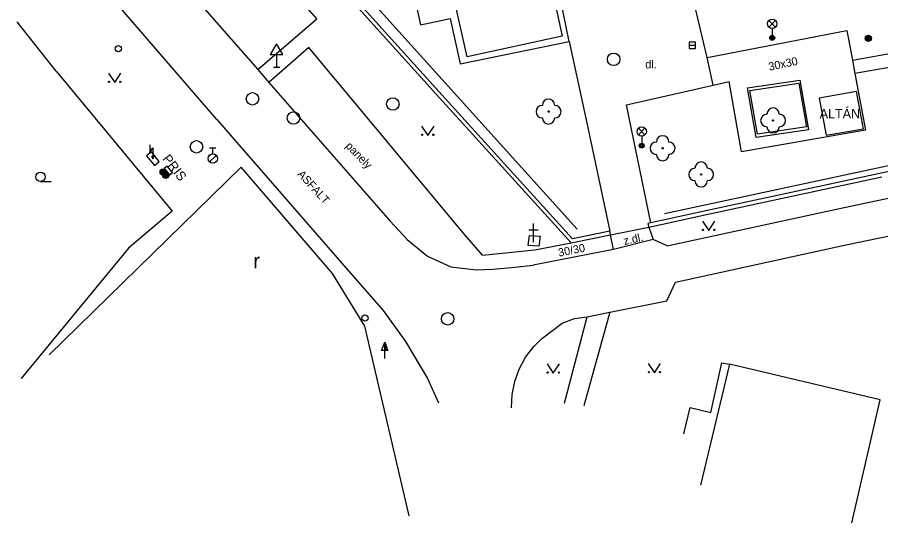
# Model space of a CAD drawing. Extents: x -539244 to -537359, y -1183785 to -1181851.
# Drawn here: x -538206 to -538136.7, y -1183773.1 to -1183732.5 of the extents above; entities that cross this region are included whole.
import ezdxf

# ---------------------------------------------------------------- set-up
doc = ezdxf.new("R2010")
doc.units = 0
for name, color, linetype in [('Vrstva 10', 7, 'Continuous'), ('Vrstva 11', 7, 'Continuous'), ('Vrstva 21', 7, 'Continuous'), ('Vrstva 22', 7, 'Continuous'), ('Vrstva 23', 7, 'Continuous'), ('Vrstva 24', 7, 'Continuous'), ('Vrstva 25', 7, 'Continuous'), ('Vrstva 27', 7, 'Continuous'), ('Vrstva 28', 7, 'Continuous'), ('Vrstva 33', 7, 'Continuous'), ('Vrstva 34', 7, 'Continuous'), ('Vrstva 36', 7, 'Continuous'), ('Vrstva 40', 7, 'Continuous'), ('Vrstva 41', 7, 'Continuous'), ('Vrstva 5', 7, 'Continuous'), ('Vrstva 7', 7, 'Continuous'), ('Vrstva 8', 7, 'Continuous')]:
    doc.layers.add(name, color=color, linetype=linetype)

msp = doc.modelspace()

# ---------------------------------------------------------------- linework, layer by layer
at = {"layer": 'Vrstva 10'}
for p, q in [((-538202.16, -1183718.96), (-538186.72, -1183736.74)), ((-538190.01, -1183740.74), (-538198.482, -1183730.899)), ((-538186.72, -1183736.74), (-538185.82, -1183737.77)), ((-538185.82, -1183737.77), (-538176.1, -1183748.9)), ((-538147.92, -1183743.33), (-538148.9, -1183737.7)), ((-538190.01, -1183740.74), (-538179.99, -1183752.25)), ((-538137.98, -1183741.61), (-538147.92, -1183743.33)), ((-538154.99, -1183750.36), (-538158.19, -1183751.17)), ((-538153.88, -1183750.89), (-538154.99, -1183750.36)), ((-538158.19, -1183751.17), (-538164.63, -1183752.42)), ((-538179.99, -1183752.25), (-538176.67, -1183756.07)), ((-538160.29, -1183756.56), (-538158.47, -1183756.19)), ((-538163.96, -1183758.34), (-538162.3, -1183757.08))]:
    msp.add_line(p, q, dxfattribs=at)
for points in [[(-538139.46, -1183733.6), (-538139.016, -1183735.982), (-538138.818, -1183737.042), (-538137.98, -1183741.61)], [(-538176.1, -1183748.9), (-538174.72, -1183750.36), (-538173.1, -1183751.7), (-538171.24, -1183752.57), (-538169.17, -1183752.81), (-538167.87, -1183752.75)], [(-538167.87, -1183752.75), (-538166.09, -1183752.58), (-538164.63, -1183752.42)], [(-538158.47, -1183756.19), (-538153.9, -1183755.3), (-538153.21, -1183753.79)], [(-538176.67, -1183756.07), (-538174.86, -1183758.55), (-538173.09, -1183761.51), (-538172.22, -1183763.48)], [(-538162.3, -1183757.08), (-538161.31, -1183756.72), (-538160.29, -1183756.56)], [(-538166.37, -1183763.88), (-538166.317, -1183762.812), (-538166.105, -1183761.763), (-538165.75, -1183760.78), (-538165.229, -1183759.818), (-538164.584, -1183758.965), (-538163.96, -1183758.34)]]:
    msp.add_lwpolyline(points, dxfattribs=at)
at = {"layer": 'Vrstva 11'}
for p, q in [((-538175.775, -1183723.409), (-538173.67, -1183733.152)), ((-538181.99, -1183732.68), (-538189.13, -1183724.3)), ((-538161.73, -1183734.48), (-538162.88, -1183729)), ((-538150.66, -1183735.78), (-538151.78, -1183731.05)), ((-538186.72, -1183736.74), (-538181.99, -1183732.68)), ((-538150.66, -1183735.78), (-538139.46, -1183733.6)), ((-538170.48, -1183736.29), (-538161.73, -1183734.48)), ((-538161.73, -1183734.48), (-538160.37, -1183740.76)), ((-538182.63, -1183734.98), (-538185.82, -1183737.77)), ((-538170.12, -1183750), (-538182.63, -1183734.98)), ((-538139.016, -1183735.982), (-538133.12, -1183734.92)), ((-538150.18, -1183737.98), (-538150.66, -1183735.78)), ((-538132.88, -1183736.01), (-538138.818, -1183737.042)), ((-538157.14, -1183739.56), (-538150.18, -1183737.98)), ((-538150.18, -1183737.98), (-538148.9, -1183737.7)), ((-538155.192, -1183749.027), (-538157.14, -1183739.56)), ((-538160.37, -1183740.76), (-538158.478, -1183749.708)), ((-538140.04, -1183747.88), (-538124.12, -1183744.52)), ((-538139.41, -1183750.76), (-538123.61, -1183747.54)), ((-538153.88, -1183750.89), (-538140.04, -1183747.88)), ((-538155.36, -1183749.37), (-538154.99, -1183750.36)), ((-538168.69, -1183751.62), (-538170.12, -1183750)), ((-538158.19, -1183751.17), (-538158.42, -1183750)), ((-538153.21, -1183753.79), (-538139.41, -1183750.76)), ((-538162.11, -1183763.5), (-538160.29, -1183756.56)), ((-538158.47, -1183756.19), (-538160.57, -1183763.71))]:
    msp.add_line(p, q, dxfattribs=at)
for points in [[(-538173.67, -1183733.152), (-538171.296, -1183732.645), (-538170.48, -1183736.29)], [(-538147.42, -1183738.21), (-538143.23, -1183737.59), (-538142.54, -1183741.56)], [(-538146.63, -1183741.91), (-538147.25, -1183738.41), (-538143.32, -1183737.829)], [(-538143.32, -1183737.829), (-538142.71, -1183741.34), (-538146.63, -1183741.91)], [(-538142.54, -1183741.56), (-538146.73, -1183742.18), (-538147.42, -1183738.21)], [(-538164.17, -1183750.9), (-538165.02, -1183750.85), (-538164.92, -1183750.04), (-538164.07, -1183750.09), (-538164.17, -1183750.9)], [(-538168.69, -1183751.62), (-538164.48, -1183751.21), (-538161.59, -1183750.64)], [(-538152.53, -1183765.96), (-538152.04, -1183763.85), (-538150.37, -1183764.24), (-538149.48, -1183760.26), (-538148.87, -1183760.36)]]:
    msp.add_lwpolyline(points, dxfattribs=at)
at = {"layer": 'Vrstva 21'}
for p, q in [((-538161.1, -1183749.528), (-538185.827, -1183722.097)), ((-538154.081, -1183748.272), (-538106.499, -1183738.062))]:
    msp.add_line(p, q, dxfattribs=at)
at = {"layer": 'Vrstva 22'}
for centre in [(-538163.39, -1183740.11), (-538145.38, -1183740.82), (-538154.24, -1183743.05), (-538151.15, -1183745.15)]:
    msp.add_circle(centre, 0.05, dxfattribs=at)
for centre, start, end in [((-538163.39, -1183739.61), 0, 180), ((-538163.89, -1183740.11), 90, 270), ((-538162.89, -1183740.11), 270, 90), ((-538145.38, -1183740.32), 0, 180), ((-538163.39, -1183740.61), 180, 0), ((-538145.88, -1183740.82), 90, 270), ((-538144.88, -1183740.82), 270, 90), ((-538145.38, -1183741.32), 180, 0), ((-538154.24, -1183742.55), 0, 180), ((-538154.74, -1183743.05), 90, 270), ((-538153.74, -1183743.05), 270, 90), ((-538154.24, -1183743.55), 180, 0), ((-538151.15, -1183744.65), 0, 180), ((-538151.65, -1183745.15), 90, 270), ((-538150.65, -1183745.15), 270, 90), ((-538151.15, -1183745.65), 180, 0)]:
    msp.add_arc(centre, 0.5, start, end, dxfattribs=at)
at = {"layer": 'Vrstva 23'}
for p, q in [((-538188.06, -1183744.58), (-538203.46, -1183759.62)), ((-538180.71, -1183753.11), (-538188.06, -1183744.58)), ((-538178.14, -1183757.31), (-538180.71, -1183753.11)), ((-538174.57, -1183772.54), (-538178.14, -1183757.31))]:
    msp.add_line(p, q, dxfattribs=at)
at = {"layer": 'Vrstva 24'}
for p, q in [((-538195.38, -1183742.764), (-538195.38, -1183743.39)), ((-538195.38, -1183743.39), (-538195.13, -1183743.015)), ((-538195.24, -1183743.645), (-538195.13, -1183743.89)), ((-538195.13, -1183743.015), (-538195.13, -1183743.89)), ((-538195.13, -1183743.89), (-538195.02, -1183743.645))]:
    msp.add_line(p, q, dxfattribs=at)
msp.add_lwpolyline([(-538194.622, -1183744.124), (-538195.248, -1183743.344), (-538195.638, -1183743.656), (-538195.012, -1183744.436)], close=True, dxfattribs=at)
msp.add_lwpolyline([(-538193.98, -1183744.48), (-538194.221, -1183744.683), (-538193.791, -1183745.193), (-538193.55, -1183744.99), (-538193.98, -1183744.48)], dxfattribs=at)
at = {"layer": 'Vrstva 25'}
for centre, radius in [((-538137.74, -1183734.23), 0.25), ((-538137.74, -1183734.23), 0.2), ((-538137.74, -1183734.23), 0.15), ((-538137.74, -1183734.23), 0.1), ((-538137.74, -1183734.23), 0.05), ((-538194.31, -1183744.96), 0.25), ((-538194.31, -1183744.96), 0.2), ((-538194.31, -1183744.96), 0.15), ((-538194.31, -1183744.96), 0.1), ((-538194.31, -1183744.96), 0.05), ((-538194.1, -1183745.23), 0.25), ((-538194.1, -1183745.23), 0.2), ((-538194.1, -1183745.23), 0.15), ((-538194.1, -1183745.23), 0.1), ((-538194.1, -1183745.23), 0.05)]:
    msp.add_circle(centre, radius, dxfattribs=at)
at = {"layer": 'Vrstva 27'}
msp.add_line((-538152.11, -1183734.79), (-538151.61, -1183734.79), dxfattribs=at)
msp.add_lwpolyline([(-538152.11, -1183735.04), (-538151.61, -1183735.04), (-538151.61, -1183734.54), (-538152.11, -1183734.54)], close=True, dxfattribs=at)
for centre in [(-538158.17, -1183735.92), (-538187.142, -1183739.083), (-538175.88, -1183739.5), (-538183.848, -1183740.625), (-538191.635, -1183742.934), (-538171.48, -1183756.73)]:
    msp.add_circle(centre, 0.5, dxfattribs=at)
at = {"layer": 'Vrstva 28'}
for p, q in [((-538190.58, -1183743.005), (-538190.08, -1183743.005)), ((-538190.33, -1183743.505), (-538190.33, -1183743.005)), ((-538190.588, -1183744.152), (-538190.058, -1183743.622)), ((-538176.781, -1183759.268), (-538176.53, -1183758.594)), ((-538176.531, -1183759.268), (-538176.781, -1183759.268)), ((-538176.53, -1183759.92), (-538176.531, -1183759.269))]:
    msp.add_line(p, q, dxfattribs=at)
for points in [[(-538176.28, -1183759.269), (-538176.531, -1183759.269), (-538176.53, -1183758.594), (-538176.28, -1183759.269)], [(-538176.337, -1183759.229), (-538176.491, -1183759.229), (-538176.49, -1183758.816)], [(-538176.395, -1183759.189), (-538176.451, -1183759.189), (-538176.451, -1183759.039)]]:
    msp.add_lwpolyline(points, close=True, dxfattribs=at)
for centre, radius in [((-538197.9, -1183735.07), 0.25), ((-538190.33, -1183743.88), 0.375), ((-538178.12, -1183756.66), 0.25)]:
    msp.add_circle(centre, radius, dxfattribs=at)
at = {"layer": 'Vrstva 33'}
for p, q in [((-538145.715, -1183733.33), (-538145.185, -1183732.8)), ((-538145.715, -1183732.8), (-538145.185, -1183733.33)), ((-538145.45, -1183733.44), (-538145.45, -1183734.19)), ((-538156.185, -1183741.98), (-538155.655, -1183741.45)), ((-538156.185, -1183741.45), (-538155.655, -1183741.98)), ((-538155.92, -1183742.09), (-538155.92, -1183742.84))]:
    msp.add_line(p, q, dxfattribs=at)
for centre, radius in [((-538145.45, -1183733.065), 0.375), ((-538145.45, -1183734.19), 0.2), ((-538145.45, -1183734.19), 0.145), ((-538145.45, -1183734.19), 0.0876), ((-538155.92, -1183741.715), 0.375), ((-538155.92, -1183742.84), 0.2), ((-538155.92, -1183742.84), 0.145), ((-538155.92, -1183742.84), 0.0876)]:
    msp.add_circle(centre, radius, dxfattribs=at)
at = {"layer": 'Vrstva 34'}
for p, q in [((-538185.21, -1183735.532), (-538185.21, -1183736.55)), ((-538185.46, -1183736.55), (-538184.96, -1183736.55))]:
    msp.add_line(p, q, dxfattribs=at)
msp.add_lwpolyline([(-538185.71, -1183735.532), (-538184.71, -1183735.532), (-538185.21, -1183734.666)], close=True, dxfattribs=at)
at = {"layer": 'Vrstva 36'}
msp.add_line((-538204.153, -1183745.722), (-538203.278, -1183745.722), dxfattribs=at)
for points in [[(-538198.696, -1183737.022), (-538198.196, -1183737.772), (-538197.696, -1183737.022)], [(-538173.579, -1183741.268), (-538173.079, -1183742.018), (-538172.579, -1183741.268)], [(-538151.044, -1183748.89), (-538150.544, -1183749.64), (-538150.044, -1183748.89)], [(-538155.402, -1183760.311), (-538154.902, -1183761.061), (-538154.402, -1183760.311)], [(-538163.516, -1183760.337), (-538163.016, -1183761.087), (-538162.516, -1183760.337)]]:
    msp.add_lwpolyline(points, dxfattribs=at)
for centre, radius in [((-538198.646, -1183737.722), 0.05), ((-538197.747, -1183737.722), 0.05), ((-538173.529, -1183741.968), 0.05), ((-538172.63, -1183741.968), 0.05), ((-538204.153, -1183745.347), 0.375), ((-538150.994, -1183749.59), 0.05), ((-538150.095, -1183749.59), 0.05), ((-538163.466, -1183761.037), 0.05), ((-538162.567, -1183761.037), 0.05), ((-538155.352, -1183761.011), 0.05), ((-538154.453, -1183761.011), 0.05)]:
    msp.add_circle(centre, radius, dxfattribs=at)
at = {"layer": 'Vrstva 41'}
for p, q in [((-538164.59, -1183750.59), (-538164.59, -1183749.09)), ((-538164.965, -1183749.59), (-538164.215, -1183749.59))]:
    msp.add_line(p, q, dxfattribs=at)
at = {"layer": 'Vrstva 5'}
for p, q in [((-538163.24, -1183729.66), (-538162.31, -1183734.07)), ((-538169.92, -1183735.71), (-538170.769, -1183731.918)), ((-538162.31, -1183734.07), (-538169.92, -1183735.71)), ((-538138.7, -1183738.51), (-538141.69, -1183739.03)), ((-538138.13, -1183741.48), (-538138.7, -1183738.51)), ((-538141.69, -1183739.03), (-538141.12, -1183742)), ((-538141.12, -1183742), (-538138.13, -1183741.48)), ((-538148.87, -1183760.36), (-538151.21, -1183770.09)), ((-538136.78, -1183763.22), (-538148.87, -1183760.36)), ((-538139.07, -1183773.09), (-538136.78, -1183763.22))]:
    msp.add_line(p, q, dxfattribs=at)
at = {"layer": 'Vrstva 7'}
for p, q in [((-538187.06, -1183722.46), (-538172.15, -1183739)), ((-538171.927, -1183738.799), (-538186.761, -1183722.343)), ((-538202.9, -1183736.86), (-538193.58, -1183748.1)), ((-538161.482, -1183750.312), (-538171.927, -1183738.799)), ((-538172.15, -1183739), (-538161.59, -1183750.64)), ((-538150.72, -1183748.37), (-538136.65, -1183745.33)), ((-538193.58, -1183748.1), (-538197.074, -1183751.062)), ((-538155.36, -1183749.37), (-538150.72, -1183748.37)), ((-538161.59, -1183750.64), (-538158.42, -1183750)), ((-538197.074, -1183751.062), (-538205.71, -1183761.51))]:
    msp.add_line(p, q, dxfattribs=at)
for points in [[(-538134.454, -1183744.573), (-538150.783, -1183748.077)], [(-538150.783, -1183748.077), (-538155.192, -1183749.027), (-538155.423, -1183749.077), (-538155.36, -1183749.37)], [(-538158.42, -1183750), (-538158.478, -1183749.708), (-538161.482, -1183750.312)]]:
    msp.add_lwpolyline(points, dxfattribs=at)
at = {"layer": 'Vrstva 8'}
for p, q in [((-538202.9, -1183736.86), (-538206.01, -1183732.92)), ((-538158.42, -1183750), (-538155.36, -1183749.37))]:
    msp.add_line(p, q, dxfattribs=at)

# ---------------------------------------------------------------- texts
at = {"layer": 'Vrstva 36'}
msp.add_text('r', height=1.2, dxfattribs=at).set_placement((-538187.077, -1183752.682))
at = {"layer": 'Vrstva 40'}
msp.add_text('dl.', height=0.65, dxfattribs=at).set_placement((-538155.629, -1183736.644))
for s, rotation, p in [('30x30', 11.86027, (-538145.673, -1183736.837)), ('panely', 314.16167, (-538179.725, -1183742.918)), ('ASFALT', 312.17424, (-538183.575, -1183745.164)), ('z.dl.', 12.54241, (-538157.304, -1183750.815)), ('30/30', 11.03007, (-538162.553, -1183751.751))]:
    msp.add_text(s, height=0.65, rotation=rotation, dxfattribs=at).set_placement(p)
at = {"layer": 'Vrstva 41'}
msp.add_text('ALTÁN', height=0.75, dxfattribs=at).set_placement((-538141.638, -1183740.643))
msp.add_text('PRIS', height=0.75, rotation=307.64762, dxfattribs=at).set_placement((-538194.397, -1183743.906))

doc.saveas('drawing.dxf')
